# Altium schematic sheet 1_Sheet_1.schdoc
size 601 x 429 mm; Symbol: Drawing-Symbol_A2; Device: Drawing-Symbol_A2; @Project Name: ESP32 SD Interrupter; @Page Count: 1; @Update Date: 2026-03-23; @Create Date: 2026-03-23; @Schematic Name: ESP32 SD Interrupter; @Page No: 1; @Page Name: Sheet_1; Version: V1.0; Page Size: A2; @Create Time: 15:58:19; @Update Time: 21:50:27; Width: 2338; Height: 1652; Region Start: 1; X Region Count: 6; Y Region Count: 4; Blade Width: 10; Title Block Position: 3; @Board Name: ESP32 SD Interrupter
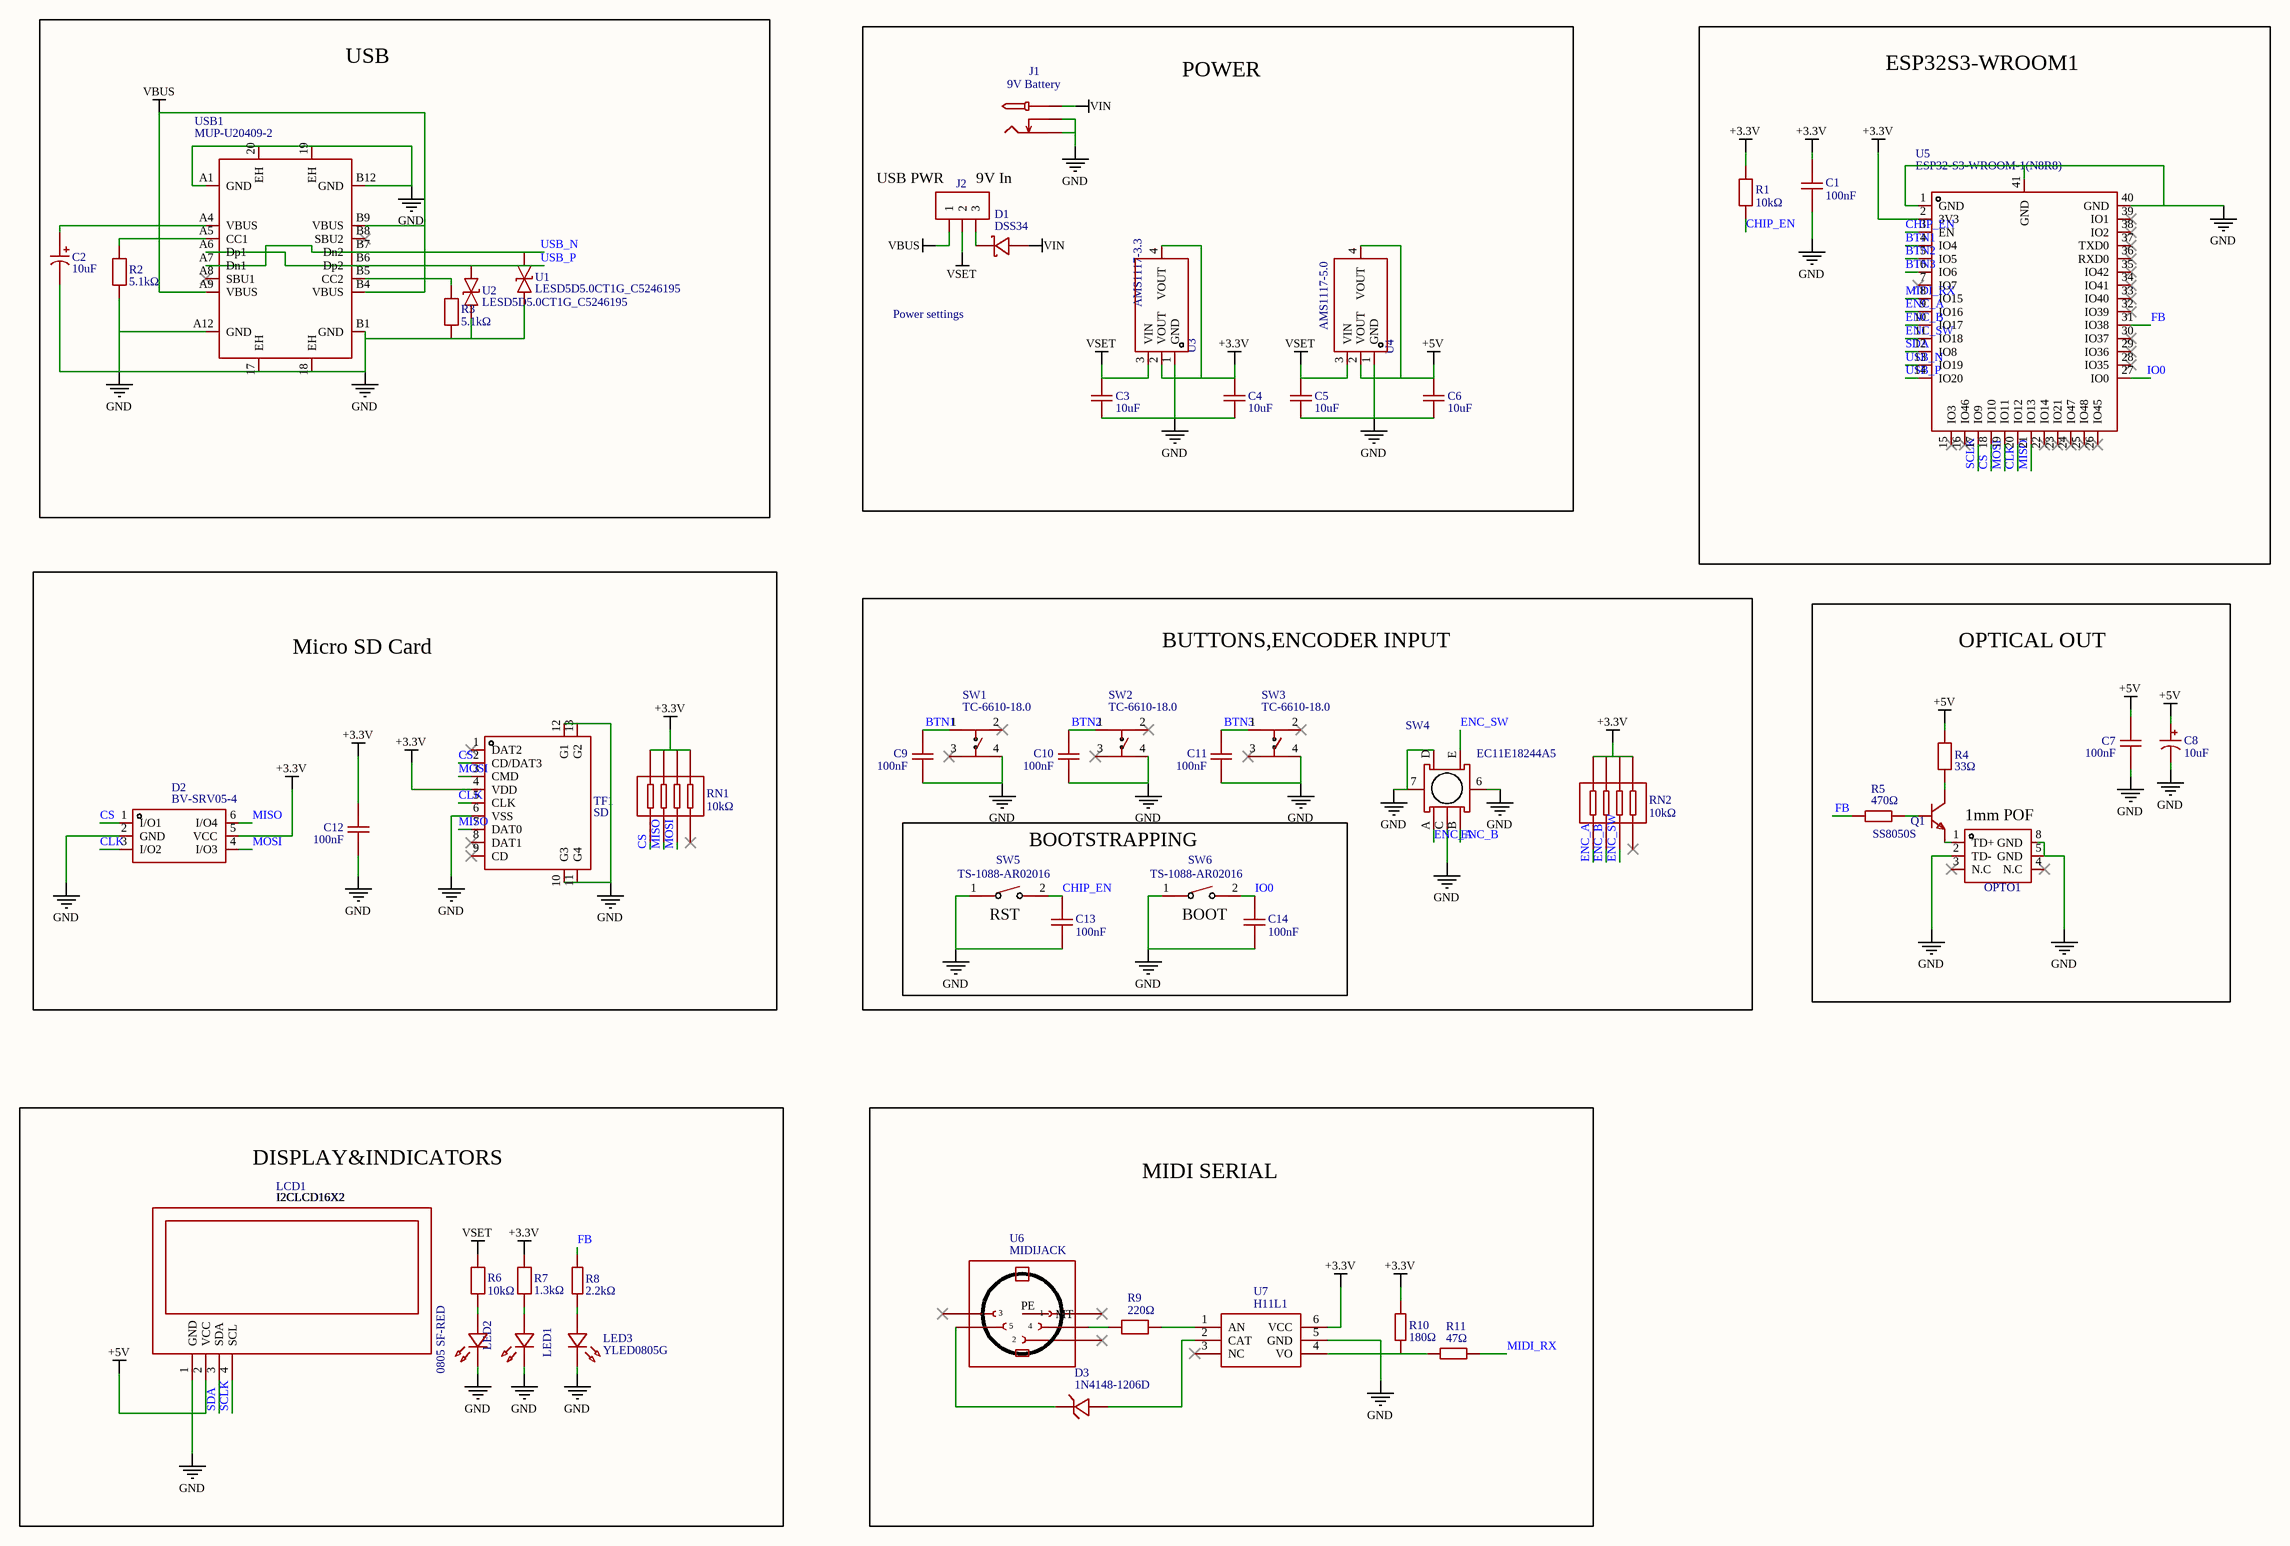
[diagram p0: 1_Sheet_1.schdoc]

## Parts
C1  100nF  [C0805]
C2  10uF  [CAP-SMD_L3.2-W2.8-FD]
C3  10uF  [C0805]
C4  10uF  [C0805]
C5  10uF  [C0805]
C6  10uF  [C0805]
C7  100nF  [C0805]
C8  10uF  [CAP-TH_BD4.0-P1.50-D0.8-FD]
C9  100nF  [C0805]
C10  100nF  [C0805]
C11  100nF  [C0805]
C12  100nF  [C0805]
C13  100nF  [C0805]
C14  100nF  [C0805]
D1  DSS34  [SOD-123_L2.8-W1.8-LS3.7-RD]
D2  BV-SRV05-4  [SOT-23-6_L2.9-W1.6-P0.95-LS2.8-BL]
D3  1N4148-1206D  [LL-34_L3.5-W1.5-R-RD]
J1  9V Battery  [DC-IN-TH_DC-5520-1]
J2  Power settings  [HDR-TH_3P-P2.54-V-M-1]
LCD1  I2CLCD16X2  [I2CLCD16X2]
LED1  0805 SF-RED  [LED0805-RD_RED]
LED2  SF-RED  [LED0805-RD_RED]  (value not drawn)
LED3  YLED0805G  [LED0805-FD-GREEN]
OPTO1  FT10MHNR_C17216617  [CONN-TH_HFBR-1521Z]  (value not drawn)
Q1  SS8050S  [SOT-23-3_L2.9-W1.3-P0.95-LS2.4-BR]
R1  10kΩ  [R0805]
R2  5.1kΩ  [R0805]
R3  5.1kΩ  [R0805]
R4  33Ω  [R0805]
R5  470Ω  [R0805]
R6  10kΩ  [R0805]
R7  1.3kΩ  [R0805]
R8  2.2kΩ  [R0805]
R9  220Ω  [R0805]
R10  180Ω  [R0805]
R11  47Ω  [R0805]
RN1  10kΩ  [RES-ARRAY-SMD_1206-8P-L5.1-W3.1-BL]
RN2  10kΩ  [RES-ARRAY-SMD_1206-8P-L5.1-W3.1-BL]
SW1  TC-6610-18.0  [SW-TH_4P-L6.0-W6.0-P4.50-LS6.5]
SW2  TC-6610-18.0  [SW-TH_4P-L6.0-W6.0-P4.50-LS6.5]
SW3  TC-6610-18.0  [SW-TH_4P-L6.0-W6.0-P4.50-LS6.5]
SW4  EC11E18244A5  [SW-TH_EC11E18244A5]
SW5  TS-1088-AR02016  [SW-SMD_L3.9-W3.0-P4.45]
SW6  TS-1088-AR02016  [SW-SMD_L3.9-W3.0-P4.45]
TF1  SD  [TF-SMD_TF-15-15]
U1  LESD5D5.0CT1G_C5246195  [SOD-523_L1.2-W0.8-LS1.6-BI]
U2  LESD5D5.0CT1G_C5246195  [SOD-523_L1.2-W0.8-LS1.6-BI]
U3  AMS1117-3.3  [SOT-223-3_L6.5-W3.4-P2.30-LS7.0-BR]
U4  AMS1117-5.0  [SOT-223_L6.5-W3.5-P2.30-LS7.0-BR]
U5  ESP32-S3-WROOM-1(N8R8)  [WIRELM-SMD_ESP32-S3-WROOM-1]
U6  MIDIJACK  [CP-2350]
U7  H11L1  [DIP-6_L8.5-W6.4-P2.54-LS7.6-BL]
USB1  MUP-U20409-2  [USB-C-SMD_MUP-U20409-2]

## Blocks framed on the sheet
USB: C2 R2 R3 U1 U2 USB1
POWER: C3-C6 D1 J1 J2 U3 U4
ESP32S3-WROOM1: C1 R1 U5
Micro SD Card: C12 D2 RN1 TF1
BUTTONS,ENCODER INPUT: C9-C11 RN2 SW1-SW4
OPTICAL OUT: C7 C8 OPTO1 Q1 R4 R5
BOOTSTRAPPING: C13 C14 SW5 SW6
DISPLAY&INDICATORS: LCD1 LED1-LED3 R6-R8
MIDI SERIAL: D3 R9-R11 U6 U7

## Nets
+3.3V: C1.2 C4.2 C12.1 D2.5(VCC) R1.2 R7.2 R10.1 RN1.5 RN1.6 RN1.7 RN1.8 RN2.5 RN2.6 RN2.7 RN2.8 TF1.4(VDD) U3.2(VOUT) U3.4(VOUT) U5.2(3V3) U7.6(VCC)
+5V: C6.2 C7.1 C8.1 LCD1.2(VCC) R4.2 U4.2(VOUT) U4.4(VOUT)
GND: C1.1 C2.2 C3.1 C4.1 C5.1 C6.1 C7.2 C8.2 C9.1 C10.1 C11.1 C12.2 C13.1 C14.1 D2.2(GND) J1.2 J1.3 LCD1.1(GND) LED1.1(K) LED2.1(K) LED3.2(K) OPTO1.2(TD-) OPTO1.5(GND) OPTO1.8(GND) R2.1 R3.1 SW1.4 SW2.4 SW3.4 SW4.6 SW4.7 SW4.C SW4.D SW5.1 SW6.1 TF1.6(VSS) TF1.10(G3) TF1.11(G4) TF1.12(G1) TF1.13(G2) U1.1 U2.1 U3.1(GND) U4.1(GND) U5.1(GND) U5.40(GND) U5.41(GND) U7.5(GND) USB1.17(EH) USB1.18(EH) USB1.19(EH) USB1.20(EH) USB1.A1(GND) USB1.A12(GND) USB1.B1(GND) USB1.B12(GND)
VBUS: C2.1 J2.1 USB1.A4(VBUS) USB1.A9(VBUS) USB1.B4(VBUS) USB1.B9(VBUS)
VIN: D1.2(A) J1.4
VSET: C3.2 C5.2 J2.2 R6.2 U3.3(VIN) U4.3(VIN)
BTN1: C9.2 SW1.1 U5.4(IO4)
BTN2: C10.2 SW2.1 U5.5(IO5)
BTN3: C11.2 SW3.1 U5.6(IO6)
CHIP_EN: C13.2 R1.1 SW5.2 U5.3(EN)
CLK: D2.3(I/O2) TF1.5(CLK) U5.20(IO12)
CS: D2.1(I/O1) RN1.1 TF1.2(CD/DAT3) U5.18(IO10)
ENC_A: RN2.1 SW4.A U5.9(IO16)
ENC_B: RN2.2 SW4.B U5.10(IO17)
ENC_SW: RN2.3 SW4.E U5.11(IO18)
FB: R5.1 R8.1 U5.31(IO38)
IO0: C14.2 SW6.2 U5.27(IO0)
MIDI_RX: R11.2 U5.8(IO15)
MISO: D2.6(I/O4) RN1.2 TF1.7(DAT0) U5.21(IO13)
MOSI: D2.4(I/O3) RN1.3 TF1.3(CMD) U5.19(IO11)
SCLK: LCD1.4(SCL) U5.17(IO9)
SDA: LCD1.3(SDA) U5.12(IO8)
USB_N: U1.2 U5.13(IO19) USB1.A7(Dn1) USB1.B7(Dn2)
USB_P: U2.2 U5.14(IO20) USB1.A6(Dp1) USB1.B6(Dp2)
NetD1_1: D1.1(K) J2.3
NetD3_1: D3.1(A) U7.2(CAT)
NetD3_2: D3.2(K) U6.5
NetLED1_2: LED1.2(A) R7.1
NetLED2_2: LED2.2(A) R6.1
NetLED3_1: LED3.1(A) R8.2
NetOPTO1_1: OPTO1.1(TD+) Q1.2(E)
NetQ1_1: Q1.1(B) R5.2
NetQ1_3: Q1.3(C) R4.1
NetR2_2: R2.2 USB1.A5(CC1)
NetR3_2: R3.2 USB1.B5(CC2)
NetR9_1: R9.1 U6.4
NetR9_2: R9.2 U7.1(AN)
NetR10_2: R10.2 R11.1 U7.4(VO)

Not connected (* = marked no-connect by the designer): OPTO1 3(N.C)* 4(N.C)*; RN1 4*; RN2 4*; SW1 2* 3*; SW2 2* 3*; SW3 2* 3*; TF1 1(DAT2)* 8(DAT1)* 9(CD)*; U5 7(IO7)* 15(IO3)* 16(IO46)* 22(IO14)* 23(IO21)* 24(IO47)* 25(IO48)* 26(IO45)* 28(IO35)* 29(IO36)* 30(IO37)* 32(IO39)* 33(IO40)* 34(IO41)* 35(IO42)* 36(RXD0)* 37(TXD0)* 38(IO2)* 39(IO1)*; U6 1* 2* 3* PE(MT); U7 3(NC)*; USB1 A8(SBU1)* B8(SBU2)*

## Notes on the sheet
- (near J2) USB PWR
- (near J2) 9V In
- 1mm POF
- (near SW5) RST
- (near SW6) BOOT

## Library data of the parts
C1 C9-C11 C13 C14 = 100nF: Manufacturer: TDK; Manufacturer Part: C2012X7R1H104KT0J0N; Convert to PCB: yes; nameAlias: Value
C2 = 10uF: Manufacturer: KEMET(基美); Manufacturer Part: T494B106K010AT; Convert to PCB: yes; nameAlias: Value; Contributor: lcsc
C3-C6 = 10uF: Manufacturer Part: CL21A106KOQNNNE; Manufacturer: SAMSUNG(三星); Convert to PCB: yes; nameAlias: Capacitance
C7 C12 = 100nF: Manufacturer: TORCH(火炬); Manufacturer Part: CC0805X7R25V104KN; Convert to PCB: yes; Contributor: lcsc; nameAlias: Value
C8 = 10uF: Manufacturer: Chengx(承兴); Manufacturer Part: KF106M025C05RR0VH2FP0; Convert to PCB: yes; nameAlias: Value
D1 = DSS34: Manufacturer: 星海; Convert to PCB: yes
D2 = BV-SRV05-4: Manufacturer: Bencent(槟城); Convert to PCB: yes; Contributor: LCSC
D3 = 1N4148-1206D: Manufacturer: null; Convert to PCB: yes; Contributor: LCSC
J1 = 9V Battery: Manufacturer: BOOMELE(博穆精密); Manufacturer Part: DC-005 2.0; Convert to PCB: yes
J2 = Power settings: Manufacturer: BOOMELE(博穆精密); Manufacturer Part: 2.54-1*3P针; Convert to PCB: yes
LCD1 = I2CLCD16X2: Convert to PCB: yes; Contributor: hobbyelectronix
LED1 = 0805 SF-RED: Manufacturer: null; Convert to PCB: yes; Contributor: lcsc
LED2 = SF-RED: Manufacturer: null; Manufacturer Part: 0805 SF-Red; Convert to PCB: yes; Contributor: lcsc
LED3 = YLED0805G: Manufacturer: YONGYUTAI(永裕泰); Convert to PCB: yes; Contributor: lcsc
OPTO1 = FT10MHNR_C17216617: Manufacturer: Firecomms; Convert to PCB: yes; Contributor: lcsc
Q1 = SS8050S: Manufacturer: FOSAN(富捷/富信); Convert to PCB: yes; Contributor: lcsc
R1 R6 = 10kΩ: Manufacturer: VISHAY(威世); Manufacturer Part: TNPW080510K0BETA; Convert to PCB: yes; nameAlias: Value; Contributor: lcsc
R2 R3 = 5.1kΩ: Manufacturer: Milliohm(毫欧); Manufacturer Part: HoAR0805-1/8W-5.1KR-0.1%-TCR25; Convert to PCB: yes; nameAlias: Value; Contributor: lcsc
R4 = 33Ω: Manufacturer: YAGEO(国巨); Manufacturer Part: SR0805FR-4733RL; Convert to PCB: yes; nameAlias: Value; Contributor: lcsc
R5 = 470Ω: Manufacturer: RESI(开步睿思); Manufacturer Part: AECR0805F470RK9; Convert to PCB: yes; nameAlias: Value; Contributor: LCSC
R7 = 1.3kΩ: Manufacturer: FOJAN(富捷); Manufacturer Part: FRQ0805F1301TS; Convert to PCB: yes; nameAlias: Value; Contributor: lcsc
R8 = 2.2kΩ: Manufacturer: Tyohm(幸亚电阻); Manufacturer Part: RMC08052.2K1%N; Convert to PCB: yes; nameAlias: Value; Contributor: LCSC
R9 = 220Ω: Manufacturer: UNI-ROYAL(厚声); Manufacturer Part: 0805W8D2200T5E; Convert to PCB: yes; nameAlias: Value; Contributor: LCSC
R10 = 180Ω: Manufacturer: UNI-ROYAL(厚声); Manufacturer Part: 0805W8F1800T5E; Convert to PCB: yes; nameAlias: Value
R11 = 47Ω: Manufacturer: UNI-ROYAL(厚声); Manufacturer Part: 0805W8F470JT5E; Convert to PCB: yes; nameAlias: Value
RN1 RN2 = 10kΩ: Manufacturer: EVER OHMS(天二科技); Manufacturer Part: CRA064RJ10K0E04Z; Convert to PCB: yes; nameAlias: Value; Contributor: LCSC
SW1-SW3 = TC-6610-18.0: Manufacturer: FG(富港); Convert to PCB: yes; Contributor: lcsc
SW4 = EC11E18244A5: Manufacturer: ALPSALPINE(阿尔卑斯阿尔派); Convert to PCB: yes; Contributor: LCSC
SW5 SW6 = TS-1088-AR02016: Manufacturer: XUNPU(讯普); Convert to PCB: yes; Contributor: LCSC
TF1 = SD: Manufacturer: null; Convert to PCB: yes; Contributor: lcsc
U1 U2 = LESD5D5.0CT1G_C5246195: Manufacturer: Leiditech(雷卯电子); Convert to PCB: yes; Contributor: lcsc
U3 = AMS1117-3.3: Manufacturer: AMS; Convert to PCB: yes; sourceId: dwIGgezVh
U4 = AMS1117-5.0: Manufacturer: AMS; Convert to PCB: yes; sourceId: HltLFyQwq
U5 = ESP32-S3-WROOM-1(N8R8): Manufacturer: ESPRESSIF(乐鑫); Manufacturer Part: ESP32-S3-WROOM-1-N8R8; Convert to PCB: yes; Contributor: LCSC
U6 = MIDIJACK: subpart_no: 3; Convert to PCB: yes; Contributor: Adafruit
U7 = H11L1: Manufacturer: EVERLIGHT(亿光); Convert to PCB: yes
USB1 = MUP-U20409-2: Manufacturer: MUP(德海威); Convert to PCB: yes; Contributor: lcsc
